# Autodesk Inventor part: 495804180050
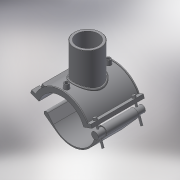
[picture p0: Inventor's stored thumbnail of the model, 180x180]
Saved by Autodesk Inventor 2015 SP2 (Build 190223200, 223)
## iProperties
Created: 2017-07
Part Number: 495804180050
Material: Generic
Description: PLASSON BRANCH SADDLE 180-50
Document SubType Name: Modeling
Designer: KIM
Density: 1 g/cm^3
Appearance: Default
Author: KIM
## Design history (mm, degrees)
derived "495804.ipt"
feature "Solid1::495804.ipt"
feature "Solid2::495804.ipt"
tag "TaggingFeature1"
body "Solid1"
body "Solid2"
other parameters: "d2" = 219, "d3" = 45, "d4" = 118, "d5" = 0, "d6" = 0.1, "d8" = 0, "d19" = 6, "d20" = 6, "d21" = 70.8, "d23" = 0, "d24" = 35.4, "d26" = 0, "d27" = 3, "d28" = 3, "d29" = 3, "d31" = 6, "d32" = 0, "d33" = 0, "d34" = 0.6, "d40" = 105.04, "d41" = 55, "d43" = 0, "d45" = 0, "d47" = 194, "d50" = 0, "d70" = 15, "d72" = 0, "d73" = 6, "d75" = 5, "d76" = 0, "d77" = 9, "d79" = 15, "d80" = 47.2, "d82" = 5 deg, "d84" = 4, "d85" = 14, "d86" = 0, "d87" = 3, "d88" = 0, "d89" = 1, "d90" = 1, "d91" = 94.4, "d92" = 0, "d93" = 0.5, "d94" = 94.73684, "d96" = 206.04, "d97" = 2.36, "d98" = 0, "d102" = 1.5, "d105" = 0, "d109" = -31, "d117" = 0.5, "d120" = 140 deg, "d121" = 24.228, "d122" = 20 deg, "d123" = 404, "d124" = 121.2, "d126" = 0, "d143" = 189, "d150" = 32.4, "d159" = 4.4, "d161" = 4.5, "d162" = 70.8, "d163" = 0, "d167" = 36, "d168" = 91.81818, "d173" = 1, "d176" = 20 deg, "d177" = 12.6, "d178" = 22, "d180" = 0, "d185" = 38.35, "d186" = 38.35, "d187" = 101, "d188" = 6.6, "d189" = 12.6, "d190" = 0, "d191" = 151.5, "d200" = 11, "d202" = 0, "d216" = 106.2, "d217" = 0, "d221" = 43.66, "d222" = 12.6, "d223" = 7.56, "d225" = 7.56, "d227" = 25.92, "d230" = 111.6, "d236" = 20 deg, "d237" = 108, "d238" = 20 deg, "d239" = 12.6, "B_" = 219, "H_" = 93, "L_" = 118, "d_t" = 6, "H_1" = 82, "d1" = 202, "d148" = 4.5, "d160" = 4.5
